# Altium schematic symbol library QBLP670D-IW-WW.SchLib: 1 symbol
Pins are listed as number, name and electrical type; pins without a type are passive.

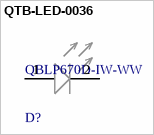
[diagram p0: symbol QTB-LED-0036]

## QTB-LED-0036
designator D?, comment QBLP670D-IW-WW
LED WARM WHITE CLEAR 2PLCC SMD; Manufacturer: QT Brightek (QTB); Lens Size: 2.4mm; Luminous Intensity: 6800mcd; Test Current: 20mA; Lens Color: Colorless; Lens Style: Round with Domed Top; Forward Voltage: 3.1V; Viewing Angle: 30°
footprint QBLP670D-IW-WW
pins: 1 ANODE (+), 2 CATHODE (-)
